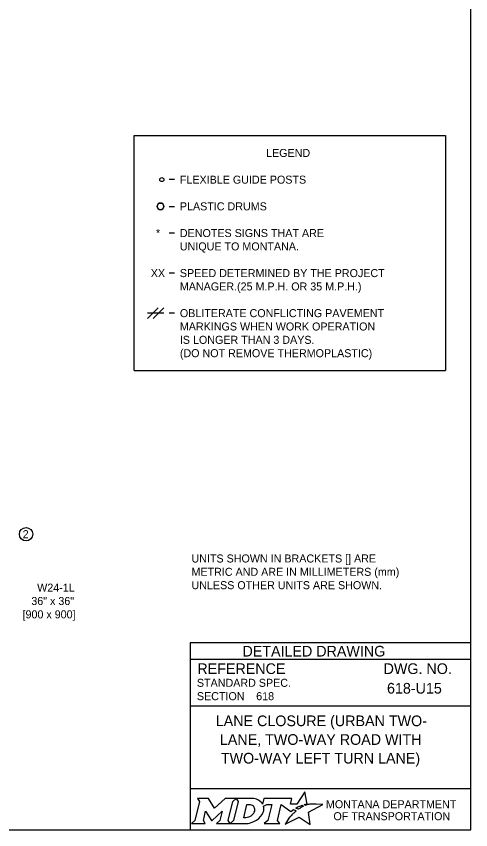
# Model space of a CAD drawing. Extents: x 49991.4 to 50021, y 49987.6 to 50011.4.
# Drawn here: x 50005.21 to 50008.61, y 50000.06 to 50006.16 of the extents above; entities that cross this region are included whole.
import ezdxf

# ---------------------------------------------------------------- set-up
doc = ezdxf.new("R2010")
doc.units = 0
doc.layers.add('Level 1', color=7, linetype='Continuous')
doc.layers.add('Level 2', color=7, linetype='Continuous')

msp = doc.modelspace()

# ---------------------------------------------------------------- linework, layer by layer
at = {"layer": 'Level 1'}
for p, q in [((50006.195, 50003.8925), (50006.275, 50003.9725)), ((50006.2374, 50003.8925), (50006.3174, 50003.9725)), ((50006.3174, 50003.9325), (50006.195, 50003.9325))]:
    msp.add_line(p, q, dxfattribs=at)
msp.add_lwpolyline([(50008.6146, 50011.2628), (50000.3356, 50011.2628), (50000.3356, 50000.0624), (50008.6146, 50000.0624)], close=True, dxfattribs=at)
for centre, radius in [((50006.3024, 50004.9325), 0.015), ((50006.2924, 50004.7325), 0.025)]:
    msp.add_circle(centre, radius, dxfattribs=at)
for start, end in [(360, 180), (180, 0)]:
    msp.add_arc((50006.2924, 50004.7325), 0.025, start, end, dxfattribs=at)
at = {"layer": 'Level 2'}
for p, q in [((50006.096, 50003.5025), (50006.096, 50005.2625)), ((50006.3974, 50004.9325), (50006.3574, 50004.9325)), ((50006.3574, 50004.7325), (50006.3974, 50004.7325)), ((50006.3974, 50004.5325), (50006.3574, 50004.5325)), ((50006.3974, 50004.2325), (50006.3574, 50004.2325)), ((50006.3974, 50003.9325), (50006.3574, 50003.9325)), ((50006.096, 50003.5025), (50008.4264, 50003.5025)), ((50008.6146, 50001.4624), (50006.5146, 50001.4624)), ((50006.5146, 50001.4624), (50006.5146, 50000.0624)), ((50008.6146, 50001.3374), (50006.5146, 50001.3374)), ((50008.2507, 50001.1223), (50008.2507, 50001.1223)), ((50007.0089, 50001.0629), (50007.0089, 50001.0629)), ((50008.6146, 50000.9874), (50006.5146, 50000.9874)), ((50007.5646, 50000.7383), (50007.5646, 50000.7383)), ((50008.6146, 50000.3693), (50006.5146, 50000.3693))]:
    msp.add_line(p, q, dxfattribs=at)
for points in [[(50006.096, 50005.2625), (50008.4264, 50005.2625), (50008.4264, 50003.5025)], [(50007.3771, 50000.2447), (50007.3668, 50000.2503), (50007.3784, 50000.2531), (50007.39, 50000.2551), (50007.3726, 50000.3452), (50007.3131, 50000.2539), (50007.2658, 50000.2532), (50007.2761, 50000.2973), (50007.0669, 50000.2974), (50007.0568, 50000.2549), (50007.051, 50000.2632)], [(50006.5701, 50000.2974), (50006.5842, 50000.274), (50006.5507, 50000.1307), (50006.525, 50000.1082), (50006.6266, 50000.1082), (50006.6131, 50000.131), (50006.6293, 50000.2011), (50006.673, 50000.1321), (50006.6783, 50000.1321), (50006.7534, 50000.2016), (50006.737, 50000.1305), (50006.7123, 50000.1085), (50006.8139, 50000.1085), (50006.8001, 50000.1318), (50006.8333, 50000.2742)], [(50006.8333, 50000.2742), (50006.8586, 50000.2974), (50006.7762, 50000.2974), (50006.6966, 50000.2244), (50006.6521, 50000.2971), (50006.5701, 50000.2974)], [(50006.9722, 50000.2974), (50006.8586, 50000.2974), (50006.8733, 50000.2745), (50006.8394, 50000.1307), (50006.8139, 50000.1085), (50006.9245, 50000.1085)], [(50006.9962, 50000.2107), (50006.995, 50000.2026), (50006.9918, 50000.1933), (50006.9876, 50000.1851), (50006.982, 50000.1776), (50006.9755, 50000.1707), (50006.9676, 50000.1644), (50006.9593, 50000.1597), (50006.9502, 50000.1558), (50006.9411, 50000.1535), (50006.9319, 50000.1526), (50006.916, 50000.1526), (50006.9396, 50000.2526), (50006.9556, 50000.2526), (50006.9632, 50000.252), (50006.9708, 50000.2501), (50006.9774, 50000.2471), (50006.9835, 50000.2429), (50006.9883, 50000.2379), (50006.992, 50000.2319), (50006.9947, 50000.2257), (50006.9963, 50000.2183), (50006.9963, 50000.2153), (50006.9962, 50000.2107)], [(50007.0636, 50000.2383), (50007.0882, 50000.2514), (50007.1251, 50000.2514), (50007.0965, 50000.1309), (50007.069, 50000.1082), (50007.1852, 50000.1082), (50007.1682, 50000.1311), (50007.1964, 50000.2513), (50007.2677, 50000.1996), (50007.2888, 50000.2147), (50007.3085, 50000.2038)], [(50007.2527, 50000.1479), (50007.2374, 50000.1235), (50007.2327, 50000.116), (50007.2269, 50000.1074), (50007.2246, 50000.1031), (50007.3299, 50000.1562), (50007.4138, 50000.1011), (50007.4007, 50000.1938), (50007.5076, 50000.2522), (50007.4583, 50000.253), (50007.4282, 50000.2534), (50007.4074, 50000.2537), (50007.4006, 50000.2522), (50007.3957, 50000.251), (50007.3873, 50000.2487), (50007.3771, 50000.2447)], [(50007.3267, 50000.2171), (50007.3243, 50000.2154), (50007.306, 50000.225), (50007.3163, 50000.2307), (50007.3204, 50000.2329), (50007.329, 50000.2369), (50007.3347, 50000.2395), (50007.3426, 50000.2425), (50007.3499, 50000.2452), (50007.3617, 50000.2378), (50007.3577, 50000.2357), (50007.3531, 50000.2332), (50007.3489, 50000.231), (50007.3439, 50000.2281), (50007.342, 50000.227), (50007.3393, 50000.2254), (50007.3368, 50000.224), (50007.3345, 50000.2224), (50007.3319, 50000.2206), (50007.3292, 50000.2188), (50007.3267, 50000.2171)], [(50006.9702, 50000.1158), (50006.9786, 50000.1184), (50006.9916, 50000.1238), (50007.012, 50000.1348)], [(50007.2666, 50000.164), (50007.2666, 50000.164)]]:
    msp.add_lwpolyline(points, dxfattribs=at)
msp.add_circle((50005.286, 50002.2766), 0.0501, dxfattribs=at)
for centre, radius, start, end in [((50006.9513, 50000.2363), 0.1183, 300.91025, 339.13831), ((50006.9953, 50000.219), 0.0709, 339.53292, 15.85821)]:
    msp.add_arc(centre, radius, start, end, dxfattribs=at)
for centre, major_axis, ratio, start_param, end_param in [((50006.9701, 50000.25), (0.0834, -0.0037), 0.568097, 0.61298, 1.570796), ((50007.0257, 50000.2573), (0.0361, -0.0295), 0.469099, 1.225588, 1.570796), ((50007.2764, 50000.1742), (-0.0098, -0.0102), 0.016458, 3.141593, 6.279097), ((50007.2974, 50000.1941), (-0.0112, -0.0097), 0.021651, 3.157348, 6.283185), ((50007.2597, 50000.1559), (-0.00694, -0.00806), 0.008222, 0, 3.137361), ((50006.9248, 50000.2568), (0, 0.1484), 0.987302, 3.139398, 3.456847)]:
    msp.add_ellipse(centre, major_axis=major_axis, ratio=ratio, start_param=start_param, end_param=end_param, dxfattribs=at)

# ---------------------------------------------------------------- texts
for s, height, p in [('LEGEND', 0.06, (50007.0828, 50005.1025)), ('FLEXIBLE GUIDE POSTS', 0.06, (50006.4374, 50004.9025)), ('PLASTIC DRUMS', 0.06, (50006.4374, 50004.7025)), ('*', 0.0601, (50006.2587, 50004.5025)), ('*', 0.06, (50006.2588, 50004.5025)), ('DENOTES SIGNS THAT ARE', 0.06, (50006.4374, 50004.5025)), ('UNIQUE TO MONTANA.', 0.06, (50006.4374, 50004.4025)), ('XX', 0.06, (50006.2196, 50004.2025)), ('SPEED DETERMINED BY THE PROJECT', 0.06, (50006.4374, 50004.2025)), ('MANAGER.(25 M.P.H. OR 35 M.P.H.)', 0.06, (50006.4374, 50004.1025)), ('OBLITERATE CONFLICTING PAVEMENT', 0.06, (50006.4374, 50003.9025)), ('MARKINGS WHEN WORK OPERATION', 0.06, (50006.4374, 50003.8025)), ('IS LONGER THAN 3 DAYS.', 0.06, (50006.4374, 50003.7025)), ('(DO NOT REMOVE THERMOPLASTIC)', 0.06, (50006.4374, 50003.6025)), ('2', 0.06, (50005.2608, 50002.2466)), ('UNITS SHOWN IN BRACKETS [] ARE ', 0.06, (50006.5243, 50002.0645)), ('METRIC AND ARE IN MILLIMETERS (mm) ', 0.06, (50006.5243, 50001.9645)), ('W24-1L', 0.06, (50005.3693, 50001.846)), ('UNLESS OTHER UNITS ARE SHOWN.', 0.06, (50006.5243, 50001.8645)), ('36" x 36"', 0.06, (50005.3254, 50001.746)), ('[900 x 900]', 0.06, (50005.2598, 50001.646)), ('DETAILED DRAWING', 0.0799, (50006.9063, 50001.3599)), ('REFERENCE', 0.08, (50006.5682, 50001.229)), ('DWG. NO.', 0.08, (50007.9624, 50001.229)), ('STANDARD SPEC.', 0.06, (50006.5649, 50001.133)), ('618-U15', 0.08, (50007.988, 50001.0823)), ('SECTION', 0.06, (50006.5649, 50001.033)), ('618', 0.06, (50007.0089, 50001.0329)), ('LANE CLOSURE (URBAN TWO-', 0.08, (50006.706, 50000.8383)), ('LANE, TWO-WAY ROAD WITH ', 0.08, (50006.7368, 50000.6983)), ('TWO-WAY LEFT TURN LANE)', 0.08, (50006.7443, 50000.5583)), ('MONTANA DEPARTMENT', 0.06, (50007.5308, 50000.2236)), ('OF TRANSPORTATION', 0.06, (50007.587, 50000.1336))]:
    msp.add_text(s, height=height, dxfattribs=at).set_placement(p)

doc.saveas('drawing.dxf')
